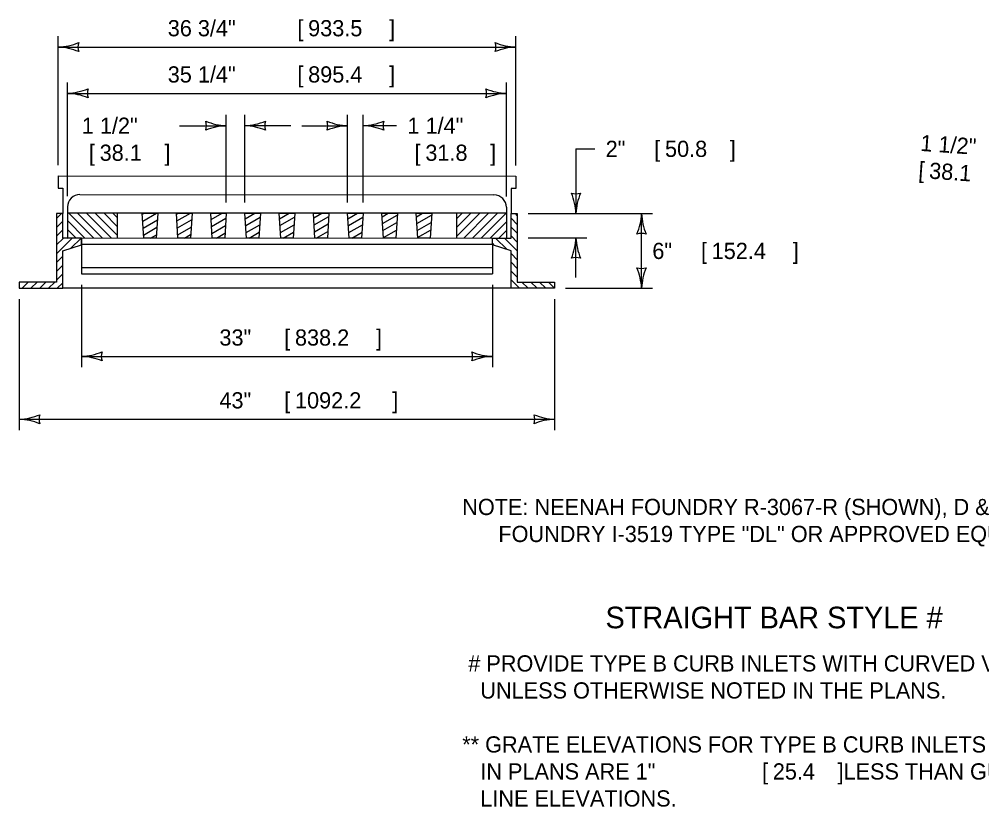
# Model space of a CAD drawing. Extents: x 49991.4 to 50057, y 49987.6 to 50011.4.
# Drawn here: x 50047.642 to 50051.205, y 49989.117 to 49992.033 of the extents above; entities that cross this region are included whole.
import ezdxf

# ---------------------------------------------------------------- set-up
doc = ezdxf.new("R2010")
doc.units = 0
for name, color, linetype in [('Level 1', 7, 'Continuous'), ('Level 2', 7, 'Continuous'), ('Level 3', 7, 'Continuous')]:
    doc.layers.add(name, color=color, linetype=linetype)

msp = doc.modelspace()

# ---------------------------------------------------------------- linework, layer by layer
at = {"layer": 'Level 1'}
for p, q in [((50047.7862, 49991.4531), (50049.4801, 49991.4517)), ((50047.7862, 49991.4531), (50047.7862, 49991.407)), ((50049.4801, 49991.4517), (50049.48, 49991.4056)), ((50047.7862, 49991.407), (50047.8035, 49991.407)), ((50047.8035, 49991.407), (50047.8035, 49991.3134)), ((50047.8669, 49991.3839), (50049.3995, 49991.3826)), ((50049.48, 49991.4056), (50049.4628, 49991.4056)), ((50049.4628, 49991.4056), (50049.4628, 49991.3134)), ((50047.7804, 49991.295), (50047.7988, 49991.3134)), ((50047.8208, 49991.3378), (50047.8208, 49991.3148)), ((50049.4455, 49991.3148), (50047.8208, 49991.3148)), ((50047.8208, 49991.3148), (50047.8208, 49991.2225)), ((50047.8258, 49991.3148), (50047.9181, 49991.2225)), ((50047.8584, 49991.3148), (50047.9507, 49991.2225)), ((50047.891, 49991.3148), (50047.9833, 49991.2225)), ((50047.9236, 49991.3148), (50048.0051, 49991.2333)), ((50047.9562, 49991.3148), (50048.0051, 49991.2659)), ((50047.9888, 49991.3148), (50048.0051, 49991.2984)), ((50048.0051, 49991.3148), (50048.0051, 49991.2225)), ((50048.0975, 49991.3111), (50048.1039, 49991.3148)), ((50048.0992, 49991.2854), (50048.15, 49991.3148)), ((50048.2243, 49991.3117), (50048.2296, 49991.3148)), ((50048.2259, 49991.286), (50048.2757, 49991.3148)), ((50048.3523, 49991.2912), (50048.3932, 49991.3148)), ((50048.4789, 49991.2944), (50048.5142, 49991.3148)), ((50048.6056, 49991.2944), (50048.641, 49991.3148)), ((50048.7322, 49991.2971), (50048.7628, 49991.3148)), ((50048.8591, 49991.2944), (50048.8945, 49991.3148)), ((50048.9854, 49991.3018), (50049.0078, 49991.3148)), ((50048.987, 49991.2761), (50049.0418, 49991.3078)), ((50049.1122, 49991.3018), (50049.1346, 49991.3148)), ((50049.1138, 49991.2761), (50049.1685, 49991.3078)), ((50049.2611, 49991.3148), (50049.2611, 49991.2239)), ((50049.2611, 49991.2289), (50049.3471, 49991.3148)), ((50049.2611, 49991.2615), (50049.3145, 49991.3148)), ((50049.2611, 49991.294), (50049.2819, 49991.3148)), ((50049.2888, 49991.2239), (50049.3796, 49991.3148)), ((50049.3213, 49991.2239), (50049.4122, 49991.3148)), ((50049.3539, 49991.2239), (50049.4448, 49991.3148)), ((50049.4455, 49991.3365), (50049.4455, 49991.3148)), ((50049.4455, 49991.3148), (50049.4455, 49991.2239)), ((50049.4779, 49991.3134), (50049.4858, 49991.3054)), ((50047.7804, 49991.2624), (50047.8035, 49991.2854)), ((50047.8208, 49991.2873), (50047.8855, 49991.2225)), ((50048.1008, 49991.2597), (50048.1534, 49991.2901)), ((50048.2275, 49991.2603), (50048.2802, 49991.2908)), ((50048.3539, 49991.2655), (50048.4073, 49991.2963)), ((50048.4805, 49991.2687), (50048.5343, 49991.2997)), ((50048.4821, 49991.243), (50048.5325, 49991.2721)), ((50048.6072, 49991.2687), (50048.661, 49991.2997)), ((50048.6088, 49991.243), (50048.6593, 49991.2721)), ((50048.7338, 49991.2714), (50048.7879, 49991.3027)), ((50048.7354, 49991.2458), (50048.7862, 49991.2751)), ((50048.8607, 49991.2687), (50048.9145, 49991.2997)), ((50048.8623, 49991.243), (50048.9128, 49991.2721)), ((50048.9886, 49991.2505), (50049.04, 49991.2802)), ((50049.1154, 49991.2505), (50049.1668, 49991.2802)), ((50049.3865, 49991.2239), (50049.4455, 49991.2829)), ((50049.4628, 49991.2959), (50049.4858, 49991.2728)), ((50047.7804, 49991.2298), (50047.8035, 49991.2529)), ((50047.8208, 49991.2547), (50047.8529, 49991.2225)), ((50048.1024, 49991.234), (50048.1517, 49991.2625)), ((50048.2291, 49991.2347), (50048.2785, 49991.2632)), ((50048.3555, 49991.2398), (50048.4056, 49991.2687)), ((50048.3718, 49991.2226), (50048.4038, 49991.2411)), ((50048.4928, 49991.2226), (50048.5308, 49991.2445)), ((50048.6196, 49991.2226), (50048.6576, 49991.2445)), ((50048.7414, 49991.2226), (50048.7845, 49991.2475)), ((50048.8731, 49991.2226), (50048.9111, 49991.2445)), ((50048.9902, 49991.2248), (50049.0383, 49991.2525)), ((50049.117, 49991.2248), (50049.1651, 49991.2525)), ((50049.4191, 49991.2239), (50049.4455, 49991.2503)), ((50049.4628, 49991.2633), (50049.4858, 49991.2402)), ((50047.7804, 49991.1646), (50047.8383, 49991.2225)), ((50047.7804, 49991.1972), (50047.8058, 49991.2225)), ((50047.8035, 49991.2249), (50047.8058, 49991.2225)), ((50047.8208, 49991.2225), (50049.4628, 49991.2239)), ((50047.8335, 49991.1851), (50047.8709, 49991.2225)), ((50047.8726, 49991.2225), (50047.8726, 49991.09)), ((50048.1286, 49991.2226), (50048.1499, 49991.2349)), ((50048.2543, 49991.2226), (50048.2767, 49991.2356)), ((50049.1593, 49991.2226), (50049.1633, 49991.2249)), ((50049.3937, 49991.202), (50049.3995, 49991.1962)), ((50049.4058, 49991.2225), (50049.4484, 49991.1799)), ((50049.4384, 49991.2225), (50049.4858, 49991.175)), ((50049.4628, 49991.2307), (50049.4858, 49991.2076)), ((50047.8726, 49991.1995), (50049.3937, 49991.1995)), ((50049.3937, 49991.1995), (50049.3937, 49991.09)), ((50049.4628, 49991.1655), (50049.4858, 49991.1425)), ((50047.7804, 49991.132), (50047.8035, 49991.1551)), ((50049.4628, 49991.1329), (50049.4858, 49991.1099)), ((50047.7804, 49991.0994), (50047.8035, 49991.1225)), ((50047.8726, 49991.1131), (50049.3937, 49991.1131)), ((50049.4628, 49991.1003), (50049.4858, 49991.0773)), ((50047.6422, 49991.0589), (50047.6431, 49991.0599)), ((50047.6526, 49991.0368), (50047.6757, 49991.0599)), ((50047.6852, 49991.0368), (50047.7083, 49991.0599)), ((50047.7178, 49991.0368), (50047.7409, 49991.0599)), ((50047.7504, 49991.0368), (50047.7735, 49991.0599)), ((50047.7804, 49991.0669), (50047.8035, 49991.0899)), ((50047.8726, 49991.09), (50049.3937, 49991.09)), ((50049.4628, 49991.0677), (50049.4937, 49991.0368)), ((50049.5032, 49991.0599), (50049.5263, 49991.0368)), ((50049.5358, 49991.0599), (50049.5589, 49991.0368)), ((50049.5684, 49991.0599), (50049.5915, 49991.0368)), ((50049.601, 49991.0599), (50049.624, 49991.0368)), ((50047.783, 49991.0368), (50047.8035, 49991.0573)), ((50049.4628, 49991.0368), (50047.8035, 49991.0368))]:
    msp.add_line(p, q, dxfattribs=at)
for points in [[(50047.7804, 49991.3134), (50047.7804, 49991.0599), (50047.6422, 49991.0599), (50047.6422, 49991.0368), (50047.8035, 49991.0368), (50047.8035, 49991.1751), (50047.8726, 49991.1982), (50047.8726, 49991.2225), (50047.8035, 49991.2225), (50047.8035, 49991.2225), (50047.8035, 49991.3134)], [(50048.1031, 49991.2226), (50048.0973, 49991.3148), (50048.1549, 49991.3148), (50048.1492, 49991.2226)], [(50048.2298, 49991.2226), (50048.2241, 49991.3148), (50048.2817, 49991.3148), (50048.2759, 49991.2226)], [(50048.3566, 49991.2226), (50048.3508, 49991.3148), (50048.4084, 49991.3148), (50048.4027, 49991.2226)], [(50048.4833, 49991.2226), (50048.4776, 49991.3148), (50048.5352, 49991.3148), (50048.5294, 49991.2226)], [(50048.6101, 49991.2226), (50048.6043, 49991.3148), (50048.6619, 49991.3148), (50048.6562, 49991.2226)], [(50048.7368, 49991.2226), (50048.7311, 49991.3148), (50048.7887, 49991.3148), (50048.7829, 49991.2226)], [(50048.8636, 49991.2226), (50048.8578, 49991.3148), (50048.9155, 49991.3148), (50048.9097, 49991.2226)], [(50048.9904, 49991.2226), (50048.9846, 49991.3148), (50049.0422, 49991.3148), (50049.0364, 49991.2226)], [(50049.1171, 49991.2226), (50049.1113, 49991.3148), (50049.169, 49991.3148), (50049.1632, 49991.2226)], [(50049.4858, 49991.3134), (50049.4858, 49991.0599), (50049.6241, 49991.0599), (50049.6241, 49991.0368), (50049.4628, 49991.0368), (50049.4628, 49991.1751), (50049.3937, 49991.1982), (50049.3937, 49991.2225), (50049.4628, 49991.2225), (50049.4628, 49991.3134)]]:
    msp.add_lwpolyline(points, close=True, dxfattribs=at)
for centre, start, end in [((50047.8669, 49991.3378), 89.9504, 180), ((50049.3994, 49991.3365), 0, 89.9504)]:
    msp.add_arc(centre, 0.0461, start, end, dxfattribs=at)
at = {"layer": 'Level 3'}
for p, q in [((50047.7862, 49991.4931), (50047.7862, 49991.9698)), ((50049.4801, 49991.4916), (50049.4801, 49991.9698)), ((50047.7862, 49991.9298), (50049.4801, 49991.9298)), ((50047.8208, 49991.3778), (50047.8208, 49991.7986)), ((50049.4455, 49991.3765), (50049.4455, 49991.7986)), ((50047.8208, 49991.7586), (50049.4455, 49991.7586)), ((50048.4084, 49991.3548), (50048.4084, 49991.6788)), ((50048.4776, 49991.3548), (50048.4776, 49991.6788)), ((50048.8578, 49991.3548), (50048.8578, 49991.6788)), ((50048.9155, 49991.3548), (50048.9155, 49991.6788)), ((50048.235, 49991.6388), (50048.4084, 49991.6388)), ((50048.6477, 49991.6388), (50048.4776, 49991.6388)), ((50048.6877, 49991.6388), (50048.8578, 49991.6388)), ((50049.0393, 49991.6388), (50048.9155, 49991.6388)), ((50049.703, 49991.5531), (50049.703, 49991.3134)), ((50049.703, 49991.5531), (50049.773, 49991.5531)), ((50049.5258, 49991.3134), (50049.9858, 49991.3134)), ((50049.9458, 49991.0368), (50049.9458, 49991.3134)), ((50049.5258, 49991.2239), (50049.743, 49991.2239)), ((50049.703, 49991.0768), (50049.703, 49991.2239)), ((50047.8726, 49991.05), (50047.8726, 49990.7444)), ((50049.3937, 49991.05), (50049.3937, 49990.7444)), ((50049.6641, 49991.0368), (50049.9858, 49991.0368)), ((50047.6422, 49990.9968), (50047.6422, 49990.5118)), ((50049.6241, 49990.9968), (50049.6241, 49990.5118)), ((50047.8726, 49990.7844), (50049.3937, 49990.7844)), ((50047.6422, 49990.5518), (50049.6241, 49990.5518))]:
    msp.add_line(p, q, dxfattribs=at)
for centre, radius, start, end in [((50047.7747, 49992.1625), 0.233, 272.8273, 292.0772), ((50047.7771, 49991.7077), 0.2223, 67.456, 87.6395), ((50047.9144, 49991.9298), 0.0548, 162.1388, 197.8612), ((50049.4892, 49992.1519), 0.2223, 247.456, 267.6395), ((50049.3519, 49991.9298), 0.0548, 342.1388, 17.8612), ((50049.4916, 49991.6971), 0.233, 92.8273, 112.0772), ((50047.8093, 49991.9913), 0.233, 272.8273, 292.0772), ((50047.949, 49991.7586), 0.0548, 162.1388, 197.8612), ((50049.4547, 49991.9807), 0.2223, 247.456, 267.6395), ((50049.3173, 49991.7586), 0.0548, 342.1388, 17.8612), ((50047.8116, 49991.5365), 0.2223, 67.456, 87.6395), ((50049.457, 49991.5259), 0.233, 92.8273, 112.0772), ((50048.4176, 49991.8609), 0.2223, 247.456, 267.6395), ((50048.2802, 49991.6388), 0.0548, 342.1388, 17.8612), ((50048.4199, 49991.4061), 0.233, 92.8273, 112.0772), ((50048.4661, 49991.8715), 0.233, 272.8273, 292.0772), ((50048.4684, 49991.4167), 0.2223, 67.456, 87.6395), ((50048.6058, 49991.6388), 0.0548, 162.1388, 197.8612), ((50048.867, 49991.8609), 0.2223, 247.456, 267.6395), ((50048.7296, 49991.6388), 0.0548, 342.1388, 17.8612), ((50048.8693, 49991.4061), 0.233, 92.8273, 112.0772), ((50048.904, 49991.8715), 0.233, 272.8273, 292.0772), ((50048.9063, 49991.4167), 0.2223, 67.456, 87.6395), ((50049.0437, 49991.6388), 0.0548, 162.1388, 197.8612), ((50049.703, 49991.4416), 0.0548, 252.1388, 287.8612), ((50049.4703, 49991.3019), 0.233, 2.8273, 22.0772), ((50049.9252, 49991.3042), 0.2223, 157.456, 177.6395), ((50049.7237, 49991.3226), 0.2223, 337.456, 357.6395), ((50050.1786, 49991.3249), 0.233, 182.8273, 202.0772), ((50049.9458, 49991.1852), 0.0548, 72.1388, 107.8612), ((50049.4809, 49991.2331), 0.2223, 337.456, 357.6395), ((50049.9357, 49991.2354), 0.233, 182.8273, 202.0772), ((50049.703, 49991.0957), 0.0548, 72.1388, 107.8612), ((50049.9458, 49991.1651), 0.0548, 252.1388, 287.8612), ((50049.7131, 49991.0253), 0.233, 2.8273, 22.0772), ((50050.168, 49991.0277), 0.2223, 157.456, 177.6395), ((50047.8611, 49991.0171), 0.233, 272.8273, 292.0772), ((50047.8635, 49990.5623), 0.2223, 67.456, 87.6395), ((50048.0008, 49990.7844), 0.0548, 162.1388, 197.8612), ((50049.4028, 49991.0066), 0.2223, 247.456, 267.6395), ((50049.2654, 49990.7844), 0.0548, 342.1388, 17.8612), ((50049.4052, 49990.5517), 0.233, 92.8273, 112.0772), ((50047.6307, 49990.7845), 0.233, 272.8273, 292.0772), ((50047.7704, 49990.5518), 0.0548, 162.1388, 197.8612), ((50049.6333, 49990.7739), 0.2223, 247.456, 267.6395), ((50049.4959, 49990.5518), 0.0548, 342.1388, 17.8612), ((50047.633, 49990.3297), 0.2223, 67.456, 87.6395), ((50049.6356, 49990.3191), 0.233, 92.8273, 112.0772)]:
    msp.add_arc(centre, radius, start, end, dxfattribs=at)

# ---------------------------------------------------------------- texts
at = {"layer": 'Level 2'}
for s, height, p in [('36 3/4" ', 0.06, (50048.1919, 49991.9698)), ('[', 0.06, (50048.6719, 49991.9698)), ('933.5', 0.06, (50048.7116, 49991.9698)), (']', 0.06, (50049.0116, 49991.9698)), ('35 1/4" ', 0.06, (50048.1919, 49991.7986)), ('[', 0.06, (50048.6719, 49991.7986)), ('895.4', 0.06, (50048.7116, 49991.7986)), (']', 0.06, (50049.0116, 49991.7986)), ('1 1/2"', 0.06, (50047.8737, 49991.6087)), ('1 1/4"', 0.06, (50049.0793, 49991.6087)), ('[', 0.06, (50047.9002, 49991.5087)), ('38.1', 0.06, (50047.9399, 49991.5087)), (']', 0.06, (50048.1799, 49991.5087)), ('[', 0.06, (50049.1058, 49991.5087)), ('31.8', 0.06, (50049.1455, 49991.5087)), (']', 0.06, (50049.3855, 49991.5087)), ('6" ', 0.06, (50049.9858, 49991.1451)), ('[', 0.06, (50050.1658, 49991.1451)), ('152.4', 0.06, (50050.2055, 49991.1451)), (']', 0.06, (50050.5055, 49991.1451)), ('33" ', 0.06, (50048.3832, 49990.8244)), ('[', 0.06, (50048.6232, 49990.8244)), ('838.2', 0.06, (50048.6629, 49990.8244)), (']', 0.06, (50048.9629, 49990.8244)), ('43" ', 0.06, (50048.3832, 49990.5918)), ('[', 0.06, (50048.6232, 49990.5918)), ('1092.2', 0.06, (50048.6629, 49990.5918)), (']', 0.06, (50049.0229, 49990.5918)), ('NOTE: NEENAH FOUNDRY R-3067-R (SHOWN), D & L', 0.06, (50049.2821, 49990.197)), ('      FOUNDRY I-3519 TYPE "DL" OR APPROVED EQUAL', 0.06, (50049.2821, 49990.097)), ('STRAIGHT BAR STYLE #', 0.08, (50049.8124, 49989.7776)), (' # PROVIDE TYPE B CURB INLETS WITH CURVED VANE', 0.06, (50049.2821, 49989.6176)), ('   UNLESS OTHERWISE NOTED IN THE PLANS. ', 0.06, (50049.2821, 49989.5176)), ('** GRATE ELEVATIONS FOR TYPE B CURB INLETS SHOWN', 0.06, (50049.2821, 49989.3176)), ('   IN PLANS ARE 1" ', 0.06, (50049.2821, 49989.2176)), ('[', 0.06, (50050.3921, 49989.2176)), ('25.4', 0.06, (50050.4318, 49989.2176)), (']', 0.06, (50050.6718, 49989.2176)), (' LESS THAN GUTTER FLOW', 0.06, (50050.6713, 49989.2176)), ('   LINE ELEVATIONS.', 0.06, (50049.2821, 49989.1176))]:
    msp.add_text(s, height=height, dxfattribs=at).set_placement(p)
for s, rotation, p in [('1 1/2"', 356, (50050.9764, 49991.5455)), ('2" ', 360, (50049.813, 49991.5231)), ('[', 360, (50049.993, 49991.5231)), ('50.8', 360, (50050.0327, 49991.5231)), (']', 360, (50050.2727, 49991.5231)), ('[', 356, (50050.9695, 49991.4457)), ('38.1', 356, (50051.009, 49991.443))]:
    msp.add_text(s, height=0.06, rotation=rotation, dxfattribs=at).set_placement(p)

doc.saveas('drawing.dxf')
